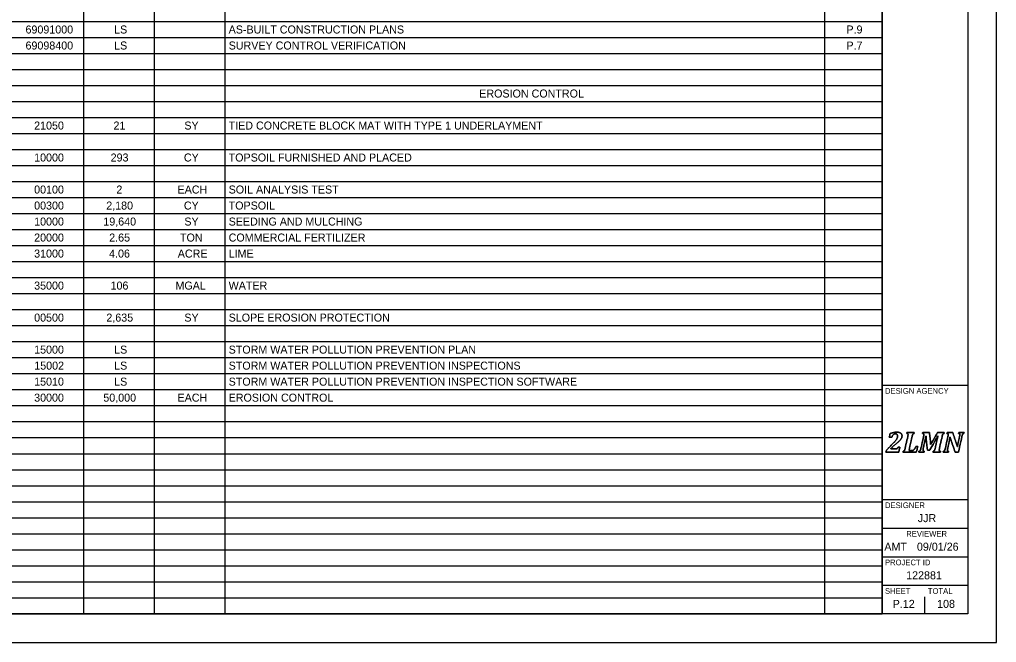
# Model space of a CAD drawing. Extents: x 0 to 34, y 0 to 22.
# Drawn here: x 16.91 to 34, y 0 to 10.9 of the extents above; entities that cross this region are included whole.
import ezdxf

# ---------------------------------------------------------------- set-up
doc = ezdxf.new("R2010")
doc.units = 0
for name, color, linetype in [('SH_Border', 7, 'Continuous'), ('SH_Cut_Line', 7, 'Continuous'), ('SH_Data', 7, 'Continuous'), ('SH_Text', 7, 'Continuous')]:
    doc.layers.add(name, color=color, linetype=linetype)

msp = doc.modelspace()

# ---------------------------------------------------------------- linework, layer by layer
at = {"layer": 'SH_Border'}
for p, q in [((32, 0.5), (32, 21.5)), ((32, 4.5), (33.5, 4.5)), ((32, 2.5), (33.5, 2.5)), ((32, 2), (33.5, 2)), ((32, 1.5), (33.5, 1.5)), ((32, 1), (33.5, 1))]:
    msp.add_line(p, q, dxfattribs=at)
msp.add_lwpolyline([(1.5, 21.5), (33.5, 21.5), (33.5, 0.5), (1.5, 0.5)], close=True, dxfattribs=at)
at = {"layer": 'SH_Cut_Line'}
msp.add_lwpolyline([(0, 0), (34, 0), (34, 22), (0, 22)], close=True, dxfattribs=at)
at = {"layer": 'SH_Data'}
for p, q in [((32.75, 3.5), (32.75, 3.5)), ((32.75, 0.5), (32.75, 0.8)), ((32.375, 0.675), (32.375, 0.675))]:
    msp.add_line(p, q, dxfattribs=at)
for points in [[(32.237, 3.388), (32.246, 3.388), (32.253, 3.389), (32.258, 3.39), (32.263, 3.392), (32.267, 3.394), (32.27, 3.397), (32.273, 3.401), (32.277, 3.408), (32.281, 3.417), (32.281, 3.417), (32.312, 3.417), (32.312, 3.417), (32.312, 3.417), (32.29, 3.326), (32.29, 3.326), (32.29, 3.326), (32.066, 3.326), (32.066, 3.326), (32.066, 3.326), (32.069, 3.343), (32.069, 3.343), (32.078, 3.358), (32.091, 3.375), (32.106, 3.394), (32.122, 3.412), (32.144, 3.435), (32.172, 3.462), (32.197, 3.486), (32.217, 3.506), (32.23, 3.521), (32.243, 3.537), (32.253, 3.551), (32.259, 3.566), (32.266, 3.58), (32.269, 3.595), (32.269, 3.61), (32.269, 3.622), (32.266, 3.632), (32.26, 3.64), (32.253, 3.647), (32.245, 3.65), (32.234, 3.65), (32.22, 3.65), (32.208, 3.646), (32.198, 3.636), (32.188, 3.627), (32.18, 3.613), (32.172, 3.593), (32.172, 3.593), (32.126, 3.593), (32.126, 3.593), (32.126, 3.593), (32.14, 3.654), (32.14, 3.654), (32.166, 3.663), (32.188, 3.669), (32.205, 3.673), (32.223, 3.676), (32.24, 3.678), (32.258, 3.678), (32.278, 3.678), (32.295, 3.675), (32.309, 3.669), (32.322, 3.664), (32.332, 3.656), (32.339, 3.646), (32.345, 3.637), (32.348, 3.626), (32.348, 3.613), (32.348, 3.602), (32.346, 3.591), (32.342, 3.581), (32.339, 3.571), (32.333, 3.56), (32.324, 3.549), (32.315, 3.539), (32.304, 3.526), (32.289, 3.513), (32.275, 3.499), (32.254, 3.482), (32.228, 3.46), (32.216, 3.45), (32.202, 3.438), (32.188, 3.425), (32.174, 3.412), (32.162, 3.4), (32.154, 3.391), (32.154, 3.391), (32.153, 3.388), (32.153, 3.388), (32.153, 3.388), (32.237, 3.388), (32.237, 3.388)], [(32.237, 3.388), (32.237, 3.388), (32.153, 3.388), (32.153, 3.388), (32.153, 3.388), (32.154, 3.391), (32.154, 3.391), (32.162, 3.4), (32.174, 3.412), (32.188, 3.425), (32.202, 3.438), (32.216, 3.45), (32.228, 3.46), (32.254, 3.482), (32.275, 3.499), (32.289, 3.513), (32.304, 3.526), (32.315, 3.539), (32.324, 3.549), (32.333, 3.56), (32.339, 3.571), (32.342, 3.581), (32.346, 3.591), (32.348, 3.602), (32.348, 3.613), (32.348, 3.626), (32.345, 3.637), (32.339, 3.646), (32.332, 3.656), (32.322, 3.664), (32.309, 3.669), (32.295, 3.675), (32.278, 3.678), (32.258, 3.678), (32.24, 3.678), (32.223, 3.676), (32.205, 3.673), (32.188, 3.669), (32.166, 3.663), (32.14, 3.654), (32.14, 3.654), (32.126, 3.593), (32.126, 3.593), (32.126, 3.593), (32.172, 3.593), (32.172, 3.593), (32.18, 3.613), (32.188, 3.627), (32.198, 3.636), (32.208, 3.646), (32.22, 3.65), (32.234, 3.65), (32.245, 3.65), (32.253, 3.647), (32.26, 3.64), (32.266, 3.632), (32.269, 3.622), (32.269, 3.61), (32.269, 3.595), (32.266, 3.58), (32.259, 3.566), (32.253, 3.551), (32.243, 3.537), (32.23, 3.521), (32.217, 3.506), (32.197, 3.486), (32.172, 3.462), (32.144, 3.435), (32.122, 3.412), (32.106, 3.394), (32.091, 3.375), (32.078, 3.358), (32.069, 3.343), (32.069, 3.343), (32.066, 3.326), (32.066, 3.326), (32.066, 3.326), (32.29, 3.326), (32.29, 3.326), (32.29, 3.326), (32.312, 3.417), (32.312, 3.417), (32.312, 3.417), (32.281, 3.417), (32.281, 3.417), (32.277, 3.408), (32.273, 3.401), (32.27, 3.397), (32.267, 3.394), (32.263, 3.392), (32.258, 3.39), (32.253, 3.389), (32.246, 3.388), (32.237, 3.388)], [(32.518, 3.356), (32.527, 3.356), (32.533, 3.357), (32.538, 3.358), (32.542, 3.36), (32.546, 3.362), (32.55, 3.365), (32.554, 3.368), (32.558, 3.372), (32.562, 3.377), (32.567, 3.382), (32.571, 3.388), (32.576, 3.397), (32.58, 3.405), (32.585, 3.415), (32.589, 3.427), (32.589, 3.427), (32.624, 3.427), (32.624, 3.427), (32.624, 3.427), (32.598, 3.326), (32.598, 3.326), (32.598, 3.326), (32.365, 3.326), (32.365, 3.326), (32.365, 3.326), (32.369, 3.343), (32.369, 3.343), (32.376, 3.345), (32.381, 3.348), (32.385, 3.351), (32.389, 3.355), (32.392, 3.36), (32.395, 3.366), (32.398, 3.373), (32.4, 3.382), (32.403, 3.395), (32.403, 3.395), (32.449, 3.605), (32.449, 3.605), (32.452, 3.615), (32.453, 3.625), (32.453, 3.635), (32.453, 3.642), (32.451, 3.647), (32.448, 3.651), (32.444, 3.654), (32.439, 3.656), (32.432, 3.657), (32.432, 3.657), (32.435, 3.674), (32.435, 3.674), (32.435, 3.674), (32.563, 3.674), (32.563, 3.674), (32.563, 3.674), (32.559, 3.657), (32.559, 3.657), (32.552, 3.655), (32.547, 3.652), (32.543, 3.649), (32.539, 3.645), (32.536, 3.64), (32.533, 3.634), (32.531, 3.627), (32.528, 3.618), (32.525, 3.605), (32.525, 3.605), (32.47, 3.356), (32.47, 3.356), (32.47, 3.356), (32.518, 3.356), (32.518, 3.356)], [(32.518, 3.356), (32.518, 3.356), (32.47, 3.356), (32.47, 3.356), (32.47, 3.356), (32.525, 3.605), (32.525, 3.605), (32.528, 3.618), (32.531, 3.627), (32.533, 3.634), (32.536, 3.64), (32.539, 3.645), (32.543, 3.649), (32.547, 3.652), (32.552, 3.655), (32.559, 3.657), (32.559, 3.657), (32.563, 3.674), (32.563, 3.674), (32.563, 3.674), (32.435, 3.674), (32.435, 3.674), (32.435, 3.674), (32.432, 3.657), (32.432, 3.657), (32.439, 3.656), (32.444, 3.654), (32.448, 3.651), (32.451, 3.647), (32.453, 3.642), (32.453, 3.635), (32.453, 3.625), (32.452, 3.615), (32.449, 3.605), (32.449, 3.605), (32.403, 3.395), (32.403, 3.395), (32.4, 3.382), (32.398, 3.373), (32.395, 3.366), (32.392, 3.36), (32.389, 3.355), (32.385, 3.351), (32.381, 3.348), (32.376, 3.345), (32.369, 3.343), (32.369, 3.343), (32.365, 3.326), (32.365, 3.326), (32.365, 3.326), (32.598, 3.326), (32.598, 3.326), (32.598, 3.326), (32.624, 3.427), (32.624, 3.427), (32.624, 3.427), (32.589, 3.427), (32.589, 3.427), (32.585, 3.415), (32.58, 3.405), (32.576, 3.397), (32.571, 3.388), (32.567, 3.382), (32.562, 3.377), (32.558, 3.372), (32.554, 3.368), (32.55, 3.365), (32.546, 3.362), (32.542, 3.36), (32.538, 3.358), (32.533, 3.357), (32.527, 3.356), (32.518, 3.356)], [(32.829, 3.674), (32.829, 3.674), (32.849, 3.461), (32.849, 3.461), (32.849, 3.461), (32.969, 3.674), (32.969, 3.674), (32.969, 3.674), (33.087, 3.674), (33.087, 3.674), (33.087, 3.674), (33.084, 3.657), (33.084, 3.657), (33.077, 3.655), (33.071, 3.652), (33.067, 3.649), (33.064, 3.645), (33.06, 3.64), (33.058, 3.634), (33.055, 3.627), (33.052, 3.618), (33.05, 3.605), (33.05, 3.605), (33.003, 3.395), (33.003, 3.395), (33.002, 3.39), (33.002, 3.387), (33.001, 3.384), (33.001, 3.382), (33.001, 3.379), (33, 3.376), (33, 3.373), (33, 3.369), (33, 3.365), (33, 3.358), (33.002, 3.353), (33.005, 3.349), (33.008, 3.346), (33.014, 3.344), (33.021, 3.343), (33.021, 3.343), (33.018, 3.326), (33.018, 3.326), (33.018, 3.326), (32.89, 3.326), (32.89, 3.326), (32.89, 3.326), (32.893, 3.343), (32.893, 3.343), (32.9, 3.345), (32.906, 3.348), (32.91, 3.351), (32.914, 3.355), (32.917, 3.36), (32.919, 3.366), (32.922, 3.373), (32.925, 3.382), (32.928, 3.395), (32.928, 3.395), (32.951, 3.502), (32.951, 3.502), (32.954, 3.513), (32.957, 3.529), (32.962, 3.548), (32.967, 3.568), (32.972, 3.588), (32.978, 3.609), (32.978, 3.609), (32.973, 3.609), (32.973, 3.609), (32.965, 3.594), (32.957, 3.579), (32.948, 3.563), (32.948, 3.563), (32.833, 3.364), (32.833, 3.364), (32.833, 3.364), (32.792, 3.364), (32.792, 3.364), (32.792, 3.364), (32.775, 3.518), (32.775, 3.518), (32.773, 3.537), (32.772, 3.554), (32.77, 3.569), (32.769, 3.583), (32.768, 3.597), (32.768, 3.611), (32.768, 3.611), (32.764, 3.611), (32.764, 3.611), (32.761, 3.596), (32.758, 3.578), (32.755, 3.558), (32.751, 3.538), (32.747, 3.521), (32.744, 3.507), (32.744, 3.507), (32.72, 3.395), (32.72, 3.395), (32.719, 3.39), (32.718, 3.387), (32.718, 3.384), (32.717, 3.382), (32.717, 3.379), (32.717, 3.376), (32.717, 3.373), (32.716, 3.369), (32.716, 3.365), (32.716, 3.358), (32.718, 3.353), (32.721, 3.349), (32.725, 3.346), (32.73, 3.344), (32.738, 3.343), (32.738, 3.343), (32.734, 3.326), (32.734, 3.326), (32.734, 3.326), (32.641, 3.326), (32.641, 3.326), (32.641, 3.326), (32.644, 3.343), (32.644, 3.343), (32.651, 3.345), (32.657, 3.348), (32.661, 3.351), (32.665, 3.355), (32.668, 3.36), (32.67, 3.366), (32.673, 3.373), (32.676, 3.382), (32.679, 3.395), (32.679, 3.395), (32.725, 3.605), (32.725, 3.605), (32.727, 3.615), (32.728, 3.625), (32.728, 3.635), (32.728, 3.642), (32.727, 3.647), (32.723, 3.651), (32.72, 3.654), (32.715, 3.656), (32.707, 3.657), (32.707, 3.657), (32.711, 3.674), (32.711, 3.674), (32.711, 3.674), (32.829, 3.674), (32.829, 3.674)], [(32.829, 3.674), (32.829, 3.674), (32.711, 3.674), (32.711, 3.674), (32.711, 3.674), (32.707, 3.657), (32.707, 3.657), (32.715, 3.656), (32.72, 3.654), (32.723, 3.651), (32.727, 3.647), (32.728, 3.642), (32.728, 3.635), (32.728, 3.625), (32.727, 3.615), (32.725, 3.605), (32.725, 3.605), (32.679, 3.395), (32.679, 3.395), (32.676, 3.382), (32.673, 3.373), (32.67, 3.366), (32.668, 3.36), (32.665, 3.355), (32.661, 3.351), (32.657, 3.348), (32.651, 3.345), (32.644, 3.343), (32.644, 3.343), (32.641, 3.326), (32.641, 3.326), (32.641, 3.326), (32.734, 3.326), (32.734, 3.326), (32.734, 3.326), (32.738, 3.343), (32.738, 3.343), (32.73, 3.344), (32.725, 3.346), (32.721, 3.349), (32.718, 3.353), (32.716, 3.358), (32.716, 3.365), (32.716, 3.369), (32.717, 3.373), (32.717, 3.376), (32.717, 3.379), (32.717, 3.382), (32.718, 3.384), (32.718, 3.387), (32.719, 3.39), (32.72, 3.395), (32.72, 3.395), (32.744, 3.507), (32.744, 3.507), (32.747, 3.521), (32.751, 3.538), (32.755, 3.558), (32.758, 3.578), (32.761, 3.596), (32.764, 3.611), (32.764, 3.611), (32.768, 3.611), (32.768, 3.611), (32.768, 3.597), (32.769, 3.583), (32.77, 3.569), (32.772, 3.554), (32.773, 3.537), (32.775, 3.518), (32.775, 3.518), (32.792, 3.364), (32.792, 3.364), (32.792, 3.364), (32.833, 3.364), (32.833, 3.364), (32.833, 3.364), (32.948, 3.563), (32.948, 3.563), (32.957, 3.579), (32.965, 3.594), (32.973, 3.609), (32.973, 3.609), (32.978, 3.609), (32.978, 3.609), (32.972, 3.588), (32.967, 3.568), (32.962, 3.548), (32.957, 3.529), (32.954, 3.513), (32.951, 3.502), (32.951, 3.502), (32.928, 3.395), (32.928, 3.395), (32.925, 3.382), (32.922, 3.373), (32.919, 3.366), (32.917, 3.36), (32.914, 3.355), (32.91, 3.351), (32.906, 3.348), (32.9, 3.345), (32.893, 3.343), (32.893, 3.343), (32.89, 3.326), (32.89, 3.326), (32.89, 3.326), (33.018, 3.326), (33.018, 3.326), (33.018, 3.326), (33.021, 3.343), (33.021, 3.343), (33.014, 3.344), (33.008, 3.346), (33.005, 3.349), (33.002, 3.353), (33, 3.358), (33, 3.365), (33, 3.369), (33, 3.373), (33, 3.376), (33.001, 3.379), (33.001, 3.382), (33.001, 3.384), (33.002, 3.387), (33.002, 3.39), (33.003, 3.395), (33.003, 3.395), (33.05, 3.605), (33.05, 3.605), (33.052, 3.618), (33.055, 3.627), (33.058, 3.634), (33.06, 3.64), (33.064, 3.645), (33.067, 3.649), (33.071, 3.652), (33.077, 3.655), (33.084, 3.657), (33.084, 3.657), (33.087, 3.674), (33.087, 3.674), (33.087, 3.674), (32.969, 3.674), (32.969, 3.674), (32.969, 3.674), (32.849, 3.461), (32.849, 3.461), (32.849, 3.461), (32.829, 3.674), (32.829, 3.674)], [(33.137, 3.674), (33.137, 3.674), (33.234, 3.674), (33.234, 3.674), (33.234, 3.674), (33.283, 3.53), (33.283, 3.53), (33.296, 3.49), (33.307, 3.456), (33.315, 3.426), (33.315, 3.426), (33.318, 3.426), (33.318, 3.426), (33.323, 3.455), (33.329, 3.488), (33.337, 3.523), (33.337, 3.523), (33.355, 3.605), (33.355, 3.605), (33.357, 3.615), (33.358, 3.625), (33.358, 3.635), (33.358, 3.642), (33.357, 3.647), (33.353, 3.651), (33.35, 3.654), (33.345, 3.656), (33.337, 3.657), (33.337, 3.657), (33.341, 3.674), (33.341, 3.674), (33.341, 3.674), (33.434, 3.674), (33.434, 3.674), (33.434, 3.674), (33.431, 3.657), (33.431, 3.657), (33.424, 3.655), (33.418, 3.652), (33.414, 3.649), (33.41, 3.645), (33.407, 3.64), (33.405, 3.634), (33.402, 3.627), (33.399, 3.618), (33.396, 3.605), (33.396, 3.605), (33.335, 3.326), (33.335, 3.326), (33.335, 3.326), (33.277, 3.326), (33.277, 3.326), (33.277, 3.326), (33.216, 3.504), (33.216, 3.504), (33.211, 3.518), (33.207, 3.531), (33.204, 3.543), (33.2, 3.556), (33.195, 3.571), (33.19, 3.59), (33.19, 3.59), (33.186, 3.59), (33.186, 3.59), (33.185, 3.579), (33.182, 3.563), (33.179, 3.543), (33.175, 3.523), (33.17, 3.501), (33.165, 3.478), (33.165, 3.478), (33.147, 3.395), (33.147, 3.395), (33.146, 3.39), (33.145, 3.387), (33.145, 3.384), (33.144, 3.382), (33.144, 3.379), (33.144, 3.376), (33.143, 3.373), (33.143, 3.369), (33.143, 3.365), (33.143, 3.358), (33.145, 3.353), (33.148, 3.349), (33.152, 3.346), (33.157, 3.344), (33.164, 3.343), (33.164, 3.343), (33.161, 3.326), (33.161, 3.326), (33.161, 3.326), (33.067, 3.326), (33.067, 3.326), (33.067, 3.326), (33.071, 3.343), (33.071, 3.343), (33.078, 3.345), (33.083, 3.348), (33.087, 3.351), (33.091, 3.355), (33.094, 3.36), (33.097, 3.366), (33.1, 3.373), (33.102, 3.382), (33.105, 3.395), (33.105, 3.395), (33.151, 3.605), (33.151, 3.605), (33.154, 3.615), (33.155, 3.625), (33.155, 3.635), (33.155, 3.642), (33.153, 3.647), (33.15, 3.651), (33.146, 3.654), (33.141, 3.656), (33.134, 3.657), (33.134, 3.657), (33.137, 3.674), (33.137, 3.674)], [(33.137, 3.674), (33.137, 3.674), (33.134, 3.657), (33.134, 3.657), (33.141, 3.656), (33.146, 3.654), (33.15, 3.651), (33.153, 3.647), (33.155, 3.642), (33.155, 3.635), (33.155, 3.625), (33.154, 3.615), (33.151, 3.605), (33.151, 3.605), (33.105, 3.395), (33.105, 3.395), (33.102, 3.382), (33.1, 3.373), (33.097, 3.366), (33.094, 3.36), (33.091, 3.355), (33.087, 3.351), (33.083, 3.348), (33.078, 3.345), (33.071, 3.343), (33.071, 3.343), (33.067, 3.326), (33.067, 3.326), (33.067, 3.326), (33.161, 3.326), (33.161, 3.326), (33.161, 3.326), (33.164, 3.343), (33.164, 3.343), (33.157, 3.344), (33.152, 3.346), (33.148, 3.349), (33.145, 3.353), (33.143, 3.358), (33.143, 3.365), (33.143, 3.369), (33.143, 3.373), (33.144, 3.376), (33.144, 3.379), (33.144, 3.382), (33.145, 3.384), (33.145, 3.387), (33.146, 3.39), (33.147, 3.395), (33.147, 3.395), (33.165, 3.478), (33.165, 3.478), (33.17, 3.501), (33.175, 3.523), (33.179, 3.543), (33.182, 3.563), (33.185, 3.579), (33.186, 3.59), (33.186, 3.59), (33.19, 3.59), (33.19, 3.59), (33.195, 3.571), (33.2, 3.556), (33.204, 3.543), (33.207, 3.531), (33.211, 3.518), (33.216, 3.504), (33.216, 3.504), (33.277, 3.326), (33.277, 3.326), (33.277, 3.326), (33.335, 3.326), (33.335, 3.326), (33.335, 3.326), (33.396, 3.605), (33.396, 3.605), (33.399, 3.618), (33.402, 3.627), (33.405, 3.634), (33.407, 3.64), (33.41, 3.645), (33.414, 3.649), (33.418, 3.652), (33.424, 3.655), (33.431, 3.657), (33.431, 3.657), (33.434, 3.674), (33.434, 3.674), (33.434, 3.674), (33.341, 3.674), (33.341, 3.674), (33.341, 3.674), (33.337, 3.657), (33.337, 3.657), (33.345, 3.656), (33.35, 3.654), (33.353, 3.651), (33.357, 3.647), (33.358, 3.642), (33.358, 3.635), (33.358, 3.625), (33.357, 3.615), (33.355, 3.605), (33.355, 3.605), (33.337, 3.523), (33.337, 3.523), (33.329, 3.488), (33.323, 3.455), (33.318, 3.426), (33.318, 3.426), (33.315, 3.426), (33.315, 3.426), (33.307, 3.456), (33.296, 3.49), (33.283, 3.53), (33.283, 3.53), (33.234, 3.674), (33.234, 3.674), (33.234, 3.674), (33.137, 3.674), (33.137, 3.674)]]:
    msp.add_open_spline(points, degree=3, dxfattribs=at)
at = {"layer": 'SH_Text'}
for p, q in [((18.035, 21.5), (18.035, 0.502)), ((19.27, 21.5), (19.27, 0.502)), ((20.505, 21.5), (20.505, 0.502)), ((30.995, 21.5), (30.995, 0.502)), ((32, 21.5), (32, 0.502)), ((1.5, 10.861), (32, 10.861)), ((1.5, 10.581), (32, 10.581)), ((1.5, 10.301), (32, 10.301)), ((1.5, 10.021), (32, 10.021)), ((1.5, 9.741), (32, 9.741)), ((1.5, 9.461), (32, 9.461)), ((1.5, 9.181), (32, 9.181)), ((1.5, 8.901), (32, 8.901)), ((1.5, 8.621), (32, 8.621)), ((1.5, 8.342), (32, 8.342)), ((1.5, 8.062), (32, 8.062)), ((1.5, 7.782), (32, 7.782)), ((1.5, 7.502), (32, 7.502)), ((1.5, 7.222), (32, 7.222)), ((1.5, 6.942), (32, 6.942)), ((1.5, 6.662), (32, 6.662)), ((1.5, 6.382), (32, 6.382)), ((1.5, 6.102), (32, 6.102)), ((1.5, 5.822), (32, 5.822)), ((1.5, 5.542), (32, 5.542)), ((1.5, 5.262), (32, 5.262)), ((1.5, 4.982), (32, 4.982)), ((1.5, 4.702), (32, 4.702)), ((1.5, 4.422), (32, 4.422)), ((1.5, 4.142), (32, 4.142)), ((1.5, 3.862), (32, 3.862)), ((1.5, 3.582), (32, 3.582)), ((1.5, 3.302), (32, 3.302)), ((1.5, 3.022), (32, 3.022)), ((1.5, 2.742), (32, 2.742)), ((1.5, 2.462), (32, 2.462)), ((1.5, 2.182), (32, 2.182)), ((1.5, 1.902), (32, 1.902)), ((1.5, 1.622), (32, 1.622)), ((1.5, 1.342), (32, 1.342)), ((1.5, 1.062), (32, 1.062)), ((1.5, 0.782), (32, 0.782)), ((1.5, 0.502), (32, 0.502))]:
    msp.add_line(p, q, dxfattribs=at)

# ---------------------------------------------------------------- texts
at = {"layer": 'SH_Data'}
for s, height, p in [('DESIGN AGENCY', 0.1, (32.05, 4.35)), ('DESIGNER', 0.1, (32.05, 2.35)), ('JJR', 0.14, (32.624, 2.105)), ('REVIEWER', 0.1, (32.422, 1.85)), ('AMT', 0.14, (32.039, 1.605)), ('09/01/26', 0.14, (32.609, 1.605)), ('PROJECT ID', 0.1, (32.05, 1.35)), ('122881', 0.14, (32.421, 1.105)), ('SHEET', 0.1, (32.05, 0.85)), ('TOTAL', 0.1, (32.8, 0.85)), ('P.12', 0.14, (32.185, 0.605)), ('108', 0.14, (32.962, 0.605))]:
    msp.add_text(s, height=height, dxfattribs=at).set_placement(p)
at = {"layer": 'SH_Text'}
for s, height, p in [('69091000', 0.14, (17.018, 10.651)), ('LS', 0.14, (18.568, 10.651)), ('AS-BUILT CONSTRUCTION PLANS', 0.13998, (20.571, 10.651)), ('P.9', 0.14, (31.376, 10.651)), ('69098400', 0.14, (17.018, 10.371)), ('LS', 0.14, (18.568, 10.371)), ('SURVEY CONTROL VERIFICATION', 0.13998, (20.571, 10.371)), ('P.7', 0.14, (31.376, 10.371)), ('EROSION CONTROL', 0.13998, (24.954, 9.531)), ('21050', 0.14, (17.169, 8.971)), ('21', 0.14, (18.557, 8.971)), ('SY', 0.14, (19.796, 8.971)), ('TIED CONCRETE BLOCK MAT WITH TYPE 1 UNDERLAYMENT', 0.13998, (20.571, 8.971)), ('10000', 0.14, (17.169, 8.412)), ('293', 0.14, (18.507, 8.412)), ('CY', 0.14, (19.788, 8.412)), ('TOPSOIL FURNISHED AND PLACED', 0.13998, (20.571, 8.412)), ('00100', 0.14, (17.169, 7.852)), ('2', 0.14, (18.607, 7.852)), ('EACH', 0.14, (19.677, 7.852)), ('SOIL ANALYSIS TEST', 0.13998, (20.571, 7.852)), ('00300', 0.14, (17.169, 7.572)), ('2,180', 0.14, (18.43, 7.572)), ('CY', 0.14, (19.788, 7.572)), ('TOPSOIL', 0.14, (20.571, 7.572)), ('10000', 0.14, (17.169, 7.292)), ('19,640', 0.14, (18.379, 7.292)), ('SY', 0.14, (19.796, 7.292)), ('SEEDING AND MULCHING', 0.13998, (20.571, 7.292)), ('20000', 0.14, (17.169, 7.012)), ('2.65', 0.14, (18.482, 7.012)), ('TON', 0.14, (19.72, 7.012)), ('COMMERCIAL FERTILIZER', 0.13998, (20.571, 7.012)), ('31000', 0.14, (17.169, 6.732)), ('4.06', 0.14, (18.48, 6.732)), ('ACRE', 0.14, (19.681, 6.732)), ('LIME', 0.14, (20.571, 6.732)), ('35000', 0.14, (17.169, 6.172)), ('106', 0.14, (18.505, 6.172)), ('MGAL', 0.14, (19.641, 6.172)), ('WATER', 0.14, (20.571, 6.172)), ('00500', 0.14, (17.169, 5.612)), ('2,635', 0.14, (18.432, 5.612)), ('SY', 0.14, (19.796, 5.612)), ('SLOPE EROSION PROTECTION', 0.13998, (20.571, 5.612)), ('15000', 0.14, (17.169, 5.052)), ('LS', 0.14, (18.568, 5.052)), ('STORM WATER POLLUTION PREVENTION PLAN', 0.13998, (20.571, 5.052)), ('15002', 0.14, (17.171, 4.772)), ('LS', 0.14, (18.568, 4.772)), ('STORM WATER POLLUTION PREVENTION INSPECTIONS', 0.13998, (20.571, 4.772)), ('15010', 0.14, (17.169, 4.492)), ('LS', 0.14, (18.568, 4.492)), ('STORM WATER POLLUTION PREVENTION INSPECTION SOFTWARE', 0.13998, (20.571, 4.492)), ('30000', 0.14, (17.169, 4.212)), ('50,000', 0.14, (18.379, 4.212)), ('EACH', 0.14, (19.677, 4.212)), ('EROSION CONTROL', 0.13998, (20.571, 4.212))]:
    msp.add_text(s, height=height, dxfattribs=at).set_placement(p)

doc.saveas('drawing.dxf')
